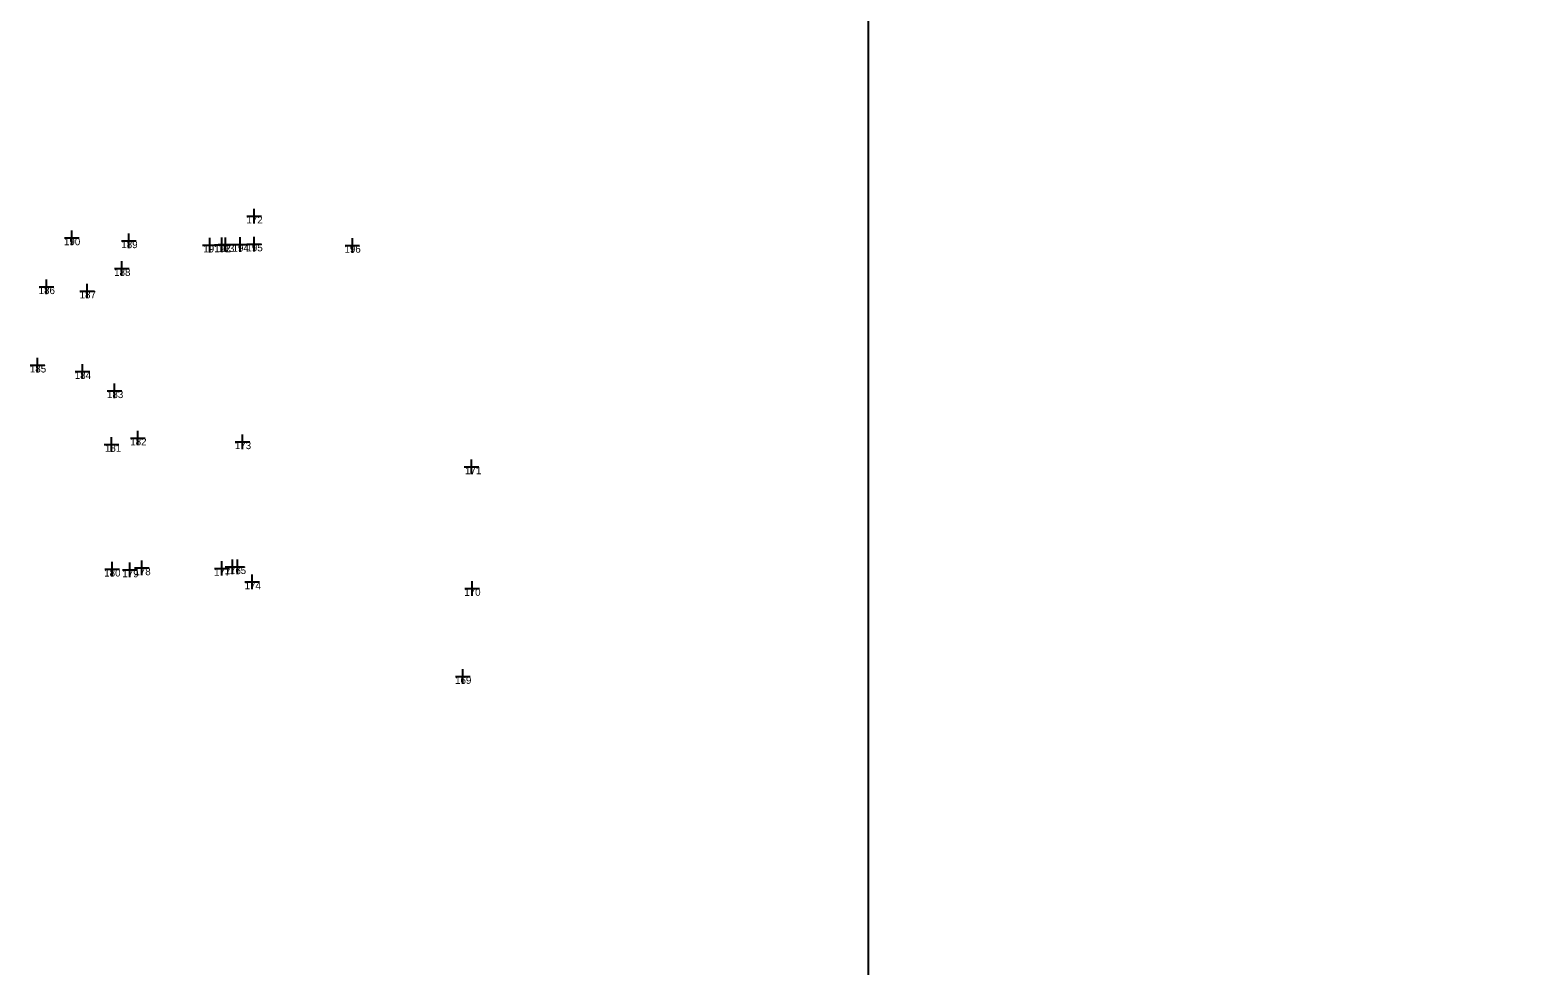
# Model space of a CAD drawing. Extents: x -706631 to -706106, y -1036183 to -1035074.
# Drawn here: x -706410.4 to -706307.4, y -1035926.8 to -1035862.9 of the extents above; entities that cross this region are included whole.
import ezdxf

# ---------------------------------------------------------------- set-up
doc = ezdxf.new("R2010")
doc.units = 0
doc.layers.add('Vrstva 54', color=7, linetype='Continuous')
doc.layers.add('čísla bodu', color=7, linetype='Continuous')

msp = doc.modelspace()

# ---------------------------------------------------------------- linework, layer by layer
at = {"layer": 'Vrstva 54'}
msp.add_lwpolyline([(-706353.14, -1035579.96), (-706108.39, -1035579.96), (-706108.39, -1035999.96), (-706353.14, -1035999.96)], close=True, dxfattribs=at)
at = {"layer": 'čísla bodu'}
for p, q in [((-706395.63, -1035875.57), (-706394.63, -1035875.57)), ((-706395.13, -1035876.07), (-706395.13, -1035875.07)), ((-706395.13, -1035875.57), (-706395.13, -1035875.57)), ((-706407.58, -1035877.56), (-706407.58, -1035876.56)), ((-706408.08, -1035877.06), (-706407.08, -1035877.06)), ((-706407.58, -1035877.06), (-706407.58, -1035877.06)), ((-706404.18, -1035877.26), (-706403.18, -1035877.26)), ((-706403.68, -1035877.76), (-706403.68, -1035876.76)), ((-706403.68, -1035877.26), (-706403.68, -1035877.26)), ((-706398.65, -1035877.55), (-706397.65, -1035877.55)), ((-706398.15, -1035878.05), (-706398.15, -1035877.05)), ((-706398.15, -1035877.55), (-706398.15, -1035877.55)), ((-706397.82, -1035877.54), (-706396.82, -1035877.54)), ((-706397.57, -1035877.52), (-706396.57, -1035877.52)), ((-706397.32, -1035878.04), (-706397.32, -1035877.04)), ((-706397.32, -1035877.54), (-706397.32, -1035877.54)), ((-706397.07, -1035878.02), (-706397.07, -1035877.02)), ((-706397.07, -1035877.52), (-706397.07, -1035877.52)), ((-706396.58, -1035877.51), (-706395.58, -1035877.51)), ((-706396.08, -1035878.01), (-706396.08, -1035877.01)), ((-706396.08, -1035877.51), (-706396.08, -1035877.51)), ((-706395.63, -1035877.48), (-706394.63, -1035877.48)), ((-706395.13, -1035877.98), (-706395.13, -1035876.98)), ((-706395.13, -1035877.48), (-706395.13, -1035877.48)), ((-706388.91, -1035877.57), (-706387.91, -1035877.57)), ((-706388.41, -1035878.07), (-706388.41, -1035877.07)), ((-706388.41, -1035877.57), (-706388.41, -1035877.57)), ((-706404.17, -1035879.66), (-706404.17, -1035878.66)), ((-706404.67, -1035879.16), (-706403.67, -1035879.16)), ((-706404.17, -1035879.16), (-706404.17, -1035879.16)), ((-706409.82, -1035880.4), (-706408.82, -1035880.4)), ((-706409.32, -1035880.9), (-706409.32, -1035879.9)), ((-706409.32, -1035880.4), (-706409.32, -1035880.4)), ((-706407.03, -1035880.69), (-706406.03, -1035880.69)), ((-706406.53, -1035881.19), (-706406.53, -1035880.19)), ((-706406.53, -1035880.69), (-706406.53, -1035880.69)), ((-706410.43, -1035885.76), (-706409.43, -1035885.76)), ((-706409.93, -1035886.26), (-706409.93, -1035885.26)), ((-706409.93, -1035885.76), (-706409.93, -1035885.76)), ((-706406.86, -1035886.7), (-706406.86, -1035885.7)), ((-706407.36, -1035886.2), (-706406.36, -1035886.2)), ((-706406.86, -1035886.2), (-706406.86, -1035886.2)), ((-706405.16, -1035887.51), (-706404.16, -1035887.51)), ((-706404.66, -1035888.01), (-706404.66, -1035887.01)), ((-706404.66, -1035887.51), (-706404.66, -1035887.51)), ((-706404.87, -1035891.68), (-706404.87, -1035890.68)), ((-706403.57, -1035890.74), (-706402.57, -1035890.74)), ((-706403.07, -1035891.24), (-706403.07, -1035890.24)), ((-706403.07, -1035890.74), (-706403.07, -1035890.74)), ((-706396.42, -1035891), (-706395.42, -1035891)), ((-706395.92, -1035891.5), (-706395.92, -1035890.5)), ((-706395.92, -1035891), (-706395.92, -1035891)), ((-706405.37, -1035891.18), (-706404.37, -1035891.18)), ((-706404.87, -1035891.18), (-706404.87, -1035891.18)), ((-706380.76, -1035892.72), (-706379.76, -1035892.72)), ((-706380.26, -1035893.22), (-706380.26, -1035892.22)), ((-706380.26, -1035892.72), (-706380.26, -1035892.72)), ((-706404.83, -1035900.21), (-706404.83, -1035899.21)), ((-706403.61, -1035900.26), (-706403.61, -1035899.26)), ((-706402.79, -1035900.12), (-706402.79, -1035899.12)), ((-706397.34, -1035900.15), (-706397.34, -1035899.15)), ((-706396.61, -1035900.05), (-706396.61, -1035899.05)), ((-706396.27, -1035900.04), (-706396.27, -1035899.04)), ((-706405.33, -1035899.71), (-706404.33, -1035899.71)), ((-706404.83, -1035899.71), (-706404.83, -1035899.71)), ((-706404.11, -1035899.76), (-706403.11, -1035899.76)), ((-706403.61, -1035899.76), (-706403.61, -1035899.76)), ((-706403.29, -1035899.62), (-706402.29, -1035899.62)), ((-706402.79, -1035899.62), (-706402.79, -1035899.62)), ((-706397.84, -1035899.65), (-706396.84, -1035899.65)), ((-706397.34, -1035899.65), (-706397.34, -1035899.65)), ((-706397.11, -1035899.55), (-706396.11, -1035899.55)), ((-706396.77, -1035899.54), (-706395.77, -1035899.54)), ((-706396.61, -1035899.55), (-706396.61, -1035899.55)), ((-706396.27, -1035899.54), (-706396.27, -1035899.54)), ((-706395.25, -1035901.08), (-706395.25, -1035900.08)), ((-706395.75, -1035900.58), (-706394.75, -1035900.58)), ((-706395.25, -1035900.58), (-706395.25, -1035900.58)), ((-706380.72, -1035901.03), (-706379.72, -1035901.03)), ((-706380.22, -1035901.53), (-706380.22, -1035900.53)), ((-706380.22, -1035901.03), (-706380.22, -1035901.03)), ((-706380.85, -1035907.55), (-706380.85, -1035906.55)), ((-706381.35, -1035907.05), (-706380.35, -1035907.05)), ((-706380.85, -1035907.05), (-706380.85, -1035907.05))]:
    msp.add_line(p, q, dxfattribs=at)

# ---------------------------------------------------------------- texts
for s, p in [('172', (-706395.65, -1035876.07)), ('190', (-706408.12, -1035877.56)), ('189', (-706404.2, -1035877.76)), ('191', (-706398.6, -1035878.05)), ('192', (-706397.84, -1035878.04)), ('193', (-706397.59, -1035878.02)), ('194', (-706396.6, -1035878.01)), ('195', (-706395.65, -1035877.98)), ('196', (-706388.95, -1035878.07)), ('188', (-706404.69, -1035879.66)), ('186', (-706409.85, -1035880.9)), ('187', (-706407.05, -1035881.19)), ('185', (-706410.45, -1035886.26)), ('184', (-706407.38, -1035886.7)), ('183', (-706405.18, -1035888.01)), ('182', (-706403.59, -1035891.24)), ('173', (-706396.44, -1035891.5)), ('181', (-706405.32, -1035891.68)), ('171', (-706380.71, -1035893.22)), ('180', (-706405.37, -1035900.21)), ('179', (-706404.13, -1035900.26)), ('178', (-706403.31, -1035900.12)), ('177', (-706397.86, -1035900.15)), ('176', (-706397.14, -1035900.05)), ('175', (-706396.79, -1035900.04)), ('174', (-706395.77, -1035901.08)), ('170', (-706380.76, -1035901.53)), ('169', (-706381.39, -1035907.55))]:
    msp.add_text(s, height=0.5, dxfattribs=at).set_placement(p)

doc.saveas('drawing.dxf')
